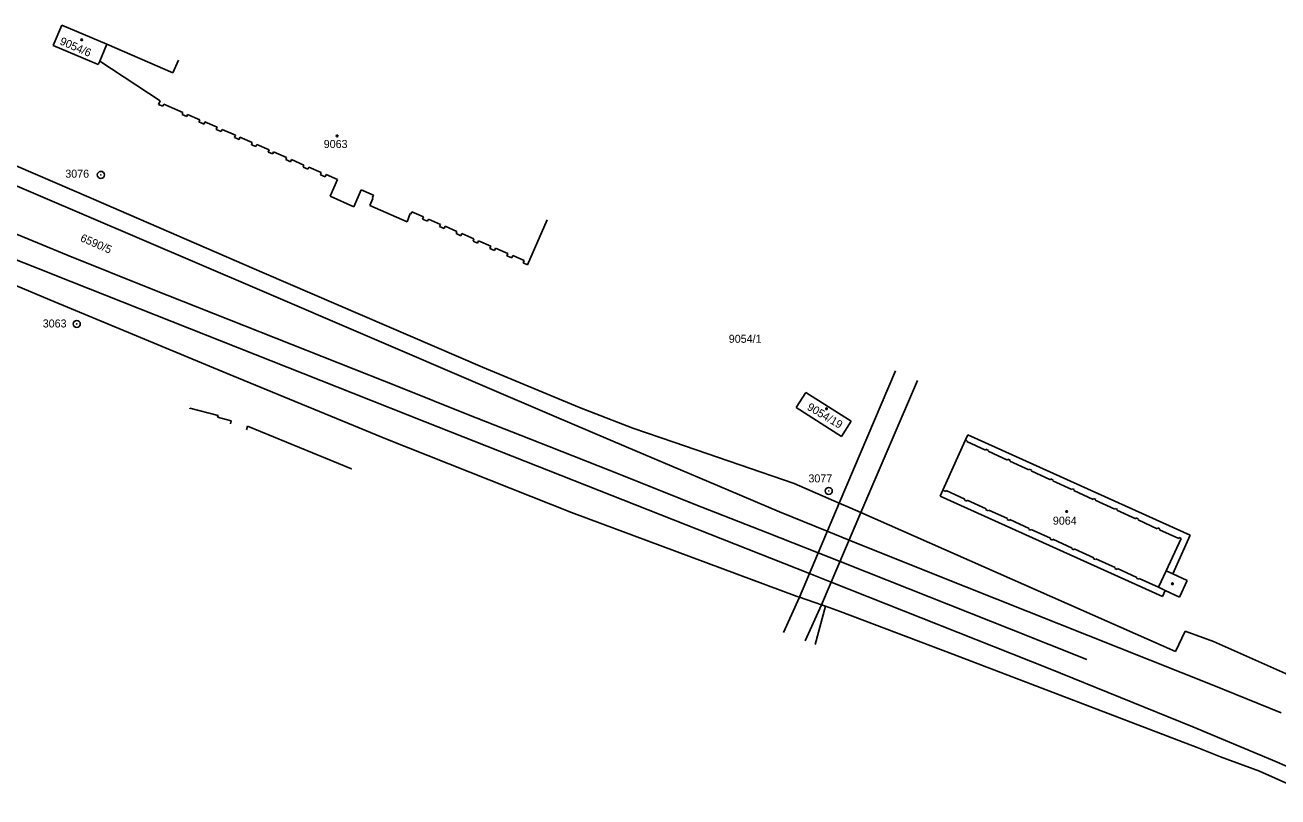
# Model space of a CAD drawing. Extents: x -825057 to -819383, y -1071633 to -1067888.
# Drawn here: x -823833 to -823566.9, y -1070247.2 to -1070083.4 of the extents above; entities that cross this region are included whole.
import ezdxf

# ---------------------------------------------------------------- set-up
doc = ezdxf.new("R2010")
doc.units = 0
for name, color, linetype in [('Vrstva 1', 7, 'Continuous'), ('Vrstva 10', 7, 'Continuous'), ('Vrstva 16', 7, 'Continuous'), ('Vrstva 17', 7, 'Continuous'), ('Vrstva 19', 7, 'Continuous'), ('Vrstva 24', 7, 'Continuous'), ('Vrstva 25', 7, 'Continuous'), ('Vrstva 4', 7, 'Continuous')]:
    doc.layers.add(name, color=color, linetype=linetype)

msp = doc.modelspace()

# ---------------------------------------------------------------- linework, layer by layer
at = {"layer": 'Vrstva 1'}
for p, q in [((-823825.21, -1070083.38), (-823827.05, -1070087.72)), ((-823815.62, -1070087.44), (-823825.21, -1070083.38)), ((-823817.15, -1070091.06), (-823815.62, -1070087.44)), ((-823815.62, -1070087.44), (-823801.63, -1070093.53)), ((-823827.05, -1070087.72), (-823817.46, -1070091.78)), ((-823817.46, -1070091.78), (-823817.15, -1070091.06)), ((-823804.33, -1070099.45), (-823817.15, -1070091.06)), ((-823801.63, -1070093.53), (-823800.4, -1070090.81)), ((-823804.67, -1070100.21), (-823804.33, -1070099.45)), ((-823803.77, -1070100.6), (-823804.67, -1070100.21)), ((-823803.57, -1070100.14), (-823803.77, -1070100.6)), ((-823799.47, -1070101.92), (-823803.57, -1070100.14)), ((-823799.66, -1070102.38), (-823799.47, -1070101.92)), ((-823798.69, -1070102.81), (-823799.66, -1070102.38)), ((-823798.49, -1070102.35), (-823798.69, -1070102.81)), ((-823795.91, -1070103.47), (-823798.49, -1070102.35)), ((-823796.11, -1070103.93), (-823795.91, -1070103.47)), ((-823795, -1070104.41), (-823796.11, -1070103.93)), ((-823794.8, -1070103.95), (-823795, -1070104.41)), ((-823792.22, -1070105.07), (-823794.8, -1070103.95)), ((-823792.42, -1070105.53), (-823792.22, -1070105.07)), ((-823791.34, -1070106), (-823792.42, -1070105.53)), ((-823791.14, -1070105.54), (-823791.34, -1070106)), ((-823788.34, -1070106.75), (-823791.14, -1070105.54)), ((-823818.96, -1070120.13), (-823850.43, -1070106.56)), ((-823788.54, -1070107.21), (-823788.34, -1070106.75)), ((-823787.57, -1070107.63), (-823788.54, -1070107.21)), ((-823787.37, -1070107.17), (-823787.57, -1070107.63)), ((-823784.74, -1070108.32), (-823787.37, -1070107.17)), ((-823784.94, -1070108.78), (-823784.74, -1070108.32)), ((-823784, -1070109.18), (-823784.94, -1070108.78)), ((-823783.8, -1070108.72), (-823784, -1070109.18)), ((-823781.17, -1070109.87), (-823783.8, -1070108.72)), ((-823781.37, -1070110.32), (-823781.17, -1070109.87)), ((-823780.41, -1070110.74), (-823781.37, -1070110.32)), ((-823780.21, -1070110.28), (-823780.41, -1070110.74)), ((-823777.45, -1070111.48), (-823780.21, -1070110.28)), ((-823777.65, -1070111.94), (-823777.45, -1070111.48)), ((-823776.62, -1070112.39), (-823777.65, -1070111.94)), ((-823776.42, -1070111.93), (-823776.62, -1070112.39)), ((-823773.77, -1070113.08), (-823776.42, -1070111.93)), ((-823773.97, -1070113.54), (-823773.77, -1070113.08)), ((-823772.94, -1070113.99), (-823773.97, -1070113.54)), ((-823772.74, -1070113.53), (-823772.94, -1070113.99)), ((-823770.09, -1070114.67), (-823772.74, -1070113.53)), ((-823770.29, -1070115.13), (-823770.09, -1070114.67)), ((-823769.28, -1070115.57), (-823770.29, -1070115.13)), ((-823769.08, -1070115.11), (-823769.28, -1070115.57)), ((-823766.66, -1070116.17), (-823769.08, -1070115.11)), ((-823768.19, -1070119.67), (-823766.66, -1070116.17)), ((-823761.61, -1070118.36), (-823763.18, -1070121.95)), ((-823758.99, -1070119.5), (-823761.61, -1070118.36)), ((-823782.23, -1070136), (-823818.96, -1070120.13)), ((-823763.18, -1070121.95), (-823768.19, -1070119.67)), ((-823759.76, -1070121.68), (-823759.11, -1070120.2)), ((-823751.87, -1070125.11), (-823759.76, -1070121.68)), ((-823759.18, -1070119.95), (-823758.99, -1070119.5)), ((-823759.11, -1070120.2), (-823759.18, -1070119.95)), ((-823751.24, -1070123.38), (-823751.87, -1070125.11)), ((-823751.05, -1070123.49), (-823751.24, -1070123.38)), ((-823750.85, -1070123.03), (-823751.05, -1070123.49)), ((-823748.36, -1070124.11), (-823750.85, -1070123.03)), ((-823748.56, -1070124.57), (-823748.36, -1070124.11)), ((-823747.54, -1070125.01), (-823748.56, -1070124.57)), ((-823747.34, -1070124.55), (-823747.54, -1070125.01)), ((-823744.75, -1070125.68), (-823747.34, -1070124.55)), ((-823722.11, -1070124.72), (-823726.26, -1070134.24)), ((-823744.95, -1070126.13), (-823744.75, -1070125.68)), ((-823744, -1070126.55), (-823744.95, -1070126.13)), ((-823743.8, -1070126.09), (-823744, -1070126.55)), ((-823741.27, -1070127.19), (-823743.8, -1070126.09)), ((-823741.47, -1070127.64), (-823741.27, -1070127.19)), ((-823827.74, -1070141.66), (-823859, -1070128.68)), ((-823740.45, -1070128.08), (-823741.47, -1070127.64)), ((-823740.26, -1070127.63), (-823740.45, -1070128.08)), ((-823737.65, -1070128.76), (-823740.26, -1070127.63)), ((-823737.85, -1070129.22), (-823737.65, -1070128.76)), ((-823736.87, -1070129.64), (-823737.85, -1070129.22)), ((-823736.67, -1070129.18), (-823736.87, -1070129.64)), ((-823734.05, -1070130.32), (-823736.67, -1070129.18)), ((-823734.25, -1070130.78), (-823734.05, -1070130.32)), ((-823733.27, -1070131.2), (-823734.25, -1070130.78)), ((-823733.07, -1070130.75), (-823733.27, -1070131.2)), ((-823730.47, -1070131.87), (-823733.07, -1070130.75)), ((-823730.67, -1070132.33), (-823730.47, -1070131.87)), ((-823729.63, -1070132.78), (-823730.67, -1070132.33)), ((-823729.43, -1070132.32), (-823729.63, -1070132.78)), ((-823726.99, -1070133.38), (-823729.43, -1070132.32)), ((-823727.19, -1070133.84), (-823726.99, -1070133.38)), ((-823726.26, -1070134.24), (-823727.19, -1070133.84)), ((-823735.81, -1070156.01), (-823782.23, -1070136)), ((-823790.07, -1070157.35), (-823827.74, -1070141.66)), ((-823715.25, -1070164.54), (-823735.81, -1070156.01)), ((-823756.05, -1070171.32), (-823790.07, -1070157.35)), ((-823669.2, -1070164.58), (-823667.12, -1070161.35)), ((-823667.12, -1070161.35), (-823657.54, -1070167.44)), ((-823798.01, -1070164.73), (-823798, -1070164.7)), ((-823798, -1070164.7), (-823792.02, -1070166.27)), ((-823703.89, -1070168.91), (-823715.25, -1070164.54)), ((-823659.56, -1070170.71), (-823669.2, -1070164.58)), ((-823792.02, -1070166.27), (-823792.12, -1070166.62)), ((-823792.12, -1070166.62), (-823789.21, -1070167.35)), ((-823789.21, -1070167.35), (-823789.37, -1070167.99)), ((-823785.98, -1070169.27), (-823785.79, -1070168.5)), ((-823785.79, -1070168.5), (-823763.69, -1070177.58)), ((-823695.2, -1070171.87), (-823703.89, -1070168.91)), ((-823657.54, -1070167.44), (-823659.56, -1070170.71)), ((-823716.94, -1070186.86), (-823756.05, -1070171.32)), ((-823669.62, -1070180.71), (-823695.2, -1070171.87)), ((-823638.04, -1070182.1), (-823633.29, -1070171.55)), ((-823633.29, -1070171.55), (-823633.23, -1070171.43)), ((-823633.23, -1070171.43), (-823632.76, -1070170.38)), ((-823632.76, -1070170.38), (-823585.51, -1070191.66)), ((-823763.72, -1070177.67), (-823763.69, -1070177.58)), ((-823660.1, -1070184.82), (-823669.62, -1070180.71)), ((-823638.61, -1070183.37), (-823638.04, -1070182.1)), ((-823657.7, -1070185.85), (-823660.1, -1070184.82)), ((-823655.46, -1070186.84), (-823657.7, -1070185.85)), ((-823591.36, -1070204.64), (-823638.61, -1070183.37)), ((-823669, -1070204.66), (-823716.94, -1070186.86)), ((-823588.59, -1070216.31), (-823655.46, -1070186.84)), ((-823585.51, -1070191.66), (-823589.21, -1070199.87)), ((-823589.21, -1070199.87), (-823586.15, -1070201.26)), ((-823586.15, -1070201.26), (-823587.74, -1070204.79)), ((-823590.79, -1070203.37), (-823591.36, -1070204.64)), ((-823587.74, -1070204.79), (-823590.79, -1070203.37)), ((-823668.52, -1070204.83), (-823669, -1070204.66)), ((-823663.8, -1070206.46), (-823668.52, -1070204.83)), ((-823665.14, -1070214.88), (-823662.99, -1070206.74)), ((-823662.99, -1070206.74), (-823663.8, -1070206.46)), ((-823659.82, -1070207.84), (-823662.99, -1070206.74)), ((-823635.91, -1070216.93), (-823659.82, -1070207.84)), ((-823586.59, -1070212.05), (-823588.59, -1070216.31)), ((-823580.56, -1070214.24), (-823586.59, -1070212.05)), ((-823547.49, -1070228.94), (-823580.56, -1070214.24)), ((-823584.03, -1070236.7), (-823635.91, -1070216.93)), ((-823579.03, -1070238.68), (-823584.03, -1070236.7)), ((-823570.77, -1070241.76), (-823579.03, -1070238.68)), ((-823567.45, -1070243.25), (-823570.77, -1070241.76)), ((-823558.51, -1070247.2), (-823567.45, -1070243.25))]:
    msp.add_line(p, q, dxfattribs=at)
at = {"layer": 'Vrstva 10'}
for p, q in [((-823820.48, -1070123.67), (-823852.48, -1070110)), ((-823783.73, -1070139.36), (-823820.48, -1070123.67)), ((-823823.85, -1070132.28), (-823836.87, -1070126.94)), ((-823827.54, -1070136.13), (-823842.18, -1070130.3)), ((-823806.26, -1070139.38), (-823823.85, -1070132.28)), ((-823827.03, -1070136.31), (-823827.54, -1070136.13)), ((-823808.63, -1070143.6), (-823827.03, -1070136.31)), ((-823753.25, -1070160.33), (-823806.26, -1070139.38)), ((-823735.84, -1070159.86), (-823783.73, -1070139.36)), ((-823763.38, -1070161.51), (-823808.63, -1070143.6)), ((-823747.99, -1070167.59), (-823763.38, -1070161.51)), ((-823739.17, -1070165.99), (-823753.25, -1070160.33)), ((-823720.59, -1070166.37), (-823735.84, -1070159.86)), ((-823721.67, -1070172.83), (-823739.17, -1070165.99)), ((-823705.3, -1070172.89), (-823720.59, -1070166.37)), ((-823666.39, -1070199.77), (-823747.99, -1070167.59)), ((-823706.21, -1070178.94), (-823721.67, -1070172.83)), ((-823685.94, -1070181.1), (-823705.3, -1070172.89)), ((-823690.84, -1070185.04), (-823706.21, -1070178.94)), ((-823672.75, -1070186.66), (-823685.94, -1070181.1)), ((-823675.26, -1070191.16), (-823690.84, -1070185.04)), ((-823662.6, -1070190.76), (-823672.75, -1070186.66)), ((-823675.26, -1070191.16), (-823664.55, -1070195.39)), ((-823657.97, -1070192.73), (-823662.6, -1070190.76)), ((-823639.76, -1070200), (-823657.97, -1070192.73)), ((-823664.55, -1070195.39), (-823659.88, -1070197.23)), ((-823659.88, -1070197.23), (-823654.34, -1070199.42)), ((-823661.74, -1070201.61), (-823666.39, -1070199.77)), ((-823615.68, -1070219.86), (-823661.74, -1070201.61)), ((-823654.34, -1070199.42), (-823623.42, -1070211.64)), ((-823580.83, -1070223.42), (-823639.76, -1070200)), ((-823623.42, -1070211.64), (-823607.42, -1070218.06)), ((-823584.9, -1070232.36), (-823615.68, -1070219.86)), ((-823566.15, -1070229.34), (-823580.83, -1070223.42)), ((-823568.02, -1070239.41), (-823584.9, -1070232.36)), ((-823556.91, -1070244.25), (-823568.02, -1070239.41))]:
    msp.add_line(p, q, dxfattribs=at)
at = {"layer": 'Vrstva 24'}
for centre, radius in [((-823816.92, -1070115.18), 0.75), ((-823816.92, -1070115.18), 0.0327), ((-823822.04, -1070146.81), 0.75), ((-823822.04, -1070146.81), 0.0327), ((-823662.27, -1070182.26), 0.75), ((-823662.27, -1070182.26), 0.0327)]:
    msp.add_circle(centre, radius, dxfattribs=at)
at = {"layer": 'Vrstva 25'}
for centre in [(-823821.01, -1070086.5), (-823766.73, -1070106.9), (-823662.76, -1070164.82), (-823611.74, -1070186.62), (-823589.26, -1070201.96)]:
    msp.add_circle(centre, 0.175, dxfattribs=at)
at = {"layer": 'Vrstva 4'}
for p, q in [((-823648.08, -1070156.79), (-823660.1, -1070184.82)), ((-823643.45, -1070158.79), (-823655.46, -1070186.84)), ((-823633.23, -1070171.43), (-823632.85, -1070171.6)), ((-823632.85, -1070171.6), (-823632.93, -1070171.78)), ((-823632.93, -1070171.78), (-823628.96, -1070173.6)), ((-823628.96, -1070173.6), (-823628.88, -1070173.41)), ((-823628.88, -1070173.41), (-823628.34, -1070173.66)), ((-823628.34, -1070173.66), (-823628.42, -1070173.84)), ((-823628.42, -1070173.84), (-823624.33, -1070175.71)), ((-823624.33, -1070175.71), (-823624.25, -1070175.53)), ((-823624.25, -1070175.53), (-823623.76, -1070175.75)), ((-823623.76, -1070175.75), (-823623.84, -1070175.94)), ((-823623.84, -1070175.94), (-823619.79, -1070177.79)), ((-823619.79, -1070177.79), (-823619.71, -1070177.61)), ((-823619.71, -1070177.61), (-823619.19, -1070177.84)), ((-823619.19, -1070177.84), (-823619.28, -1070178.02)), ((-823619.28, -1070178.02), (-823615.17, -1070179.9)), ((-823615.17, -1070179.9), (-823615.09, -1070179.72)), ((-823615.09, -1070179.72), (-823614.59, -1070179.95)), ((-823614.59, -1070179.95), (-823614.67, -1070180.13)), ((-823614.67, -1070180.13), (-823610.62, -1070181.98)), ((-823637.43, -1070182.37), (-823638.04, -1070182.1)), ((-823637.35, -1070182.19), (-823637.43, -1070182.37)), ((-823633.34, -1070184.01), (-823637.35, -1070182.19)), ((-823610.62, -1070181.98), (-823610.53, -1070181.8)), ((-823610.53, -1070181.8), (-823610.14, -1070181.98)), ((-823610.14, -1070181.98), (-823610.22, -1070182.16)), ((-823610.22, -1070182.16), (-823606.1, -1070184.04)), ((-823660.1, -1070184.82), (-823668.52, -1070204.83)), ((-823633.43, -1070184.2), (-823633.34, -1070184.01)), ((-823632.93, -1070184.42), (-823633.43, -1070184.2)), ((-823632.85, -1070184.24), (-823632.93, -1070184.42)), ((-823628.82, -1070186.07), (-823632.85, -1070184.24)), ((-823606.1, -1070184.04), (-823606.02, -1070183.86)), ((-823606.02, -1070183.86), (-823605.57, -1070184.07)), ((-823605.57, -1070184.07), (-823605.65, -1070184.25)), ((-823605.65, -1070184.25), (-823601.51, -1070186.14)), ((-823601.51, -1070186.14), (-823601.43, -1070185.96)), ((-823601.43, -1070185.96), (-823600.97, -1070186.17)), ((-823655.46, -1070186.84), (-823663.8, -1070206.46)), ((-823628.9, -1070186.25), (-823628.82, -1070186.07)), ((-823628.35, -1070186.5), (-823628.9, -1070186.25)), ((-823628.27, -1070186.32), (-823628.35, -1070186.5)), ((-823624.3, -1070188.12), (-823628.27, -1070186.32)), ((-823624.39, -1070188.3), (-823624.3, -1070188.12)), ((-823623.91, -1070188.52), (-823624.39, -1070188.3)), ((-823623.83, -1070188.34), (-823623.91, -1070188.52)), ((-823619.68, -1070190.23), (-823623.83, -1070188.34)), ((-823600.97, -1070186.17), (-823601.06, -1070186.35)), ((-823601.06, -1070186.35), (-823597.05, -1070188.18)), ((-823597.05, -1070188.18), (-823596.97, -1070188)), ((-823596.97, -1070188), (-823596.48, -1070188.22)), ((-823596.48, -1070188.22), (-823596.56, -1070188.4)), ((-823596.56, -1070188.4), (-823592.48, -1070190.27)), ((-823619.76, -1070190.41), (-823619.68, -1070190.23)), ((-823619.35, -1070190.6), (-823619.76, -1070190.41)), ((-823619.26, -1070190.41), (-823619.35, -1070190.6)), ((-823615.16, -1070192.28), (-823619.26, -1070190.41)), ((-823592.48, -1070190.27), (-823592.4, -1070190.09)), ((-823592.4, -1070190.09), (-823591.93, -1070190.3)), ((-823591.93, -1070190.3), (-823592.01, -1070190.48)), ((-823592.01, -1070190.48), (-823587.94, -1070192.34)), ((-823615.24, -1070192.46), (-823615.16, -1070192.28)), ((-823614.78, -1070192.67), (-823615.24, -1070192.46)), ((-823614.7, -1070192.49), (-823614.78, -1070192.67)), ((-823610.54, -1070194.38), (-823614.7, -1070192.49)), ((-823587.41, -1070192.37), (-823590.61, -1070199.23)), ((-823587.94, -1070192.34), (-823587.86, -1070192.16)), ((-823587.86, -1070192.16), (-823587.41, -1070192.37)), ((-823610.62, -1070194.56), (-823610.54, -1070194.38)), ((-823610.22, -1070194.74), (-823610.62, -1070194.56)), ((-823610.14, -1070194.56), (-823610.22, -1070194.74)), ((-823605.94, -1070196.47), (-823610.14, -1070194.56)), ((-823606.02, -1070196.65), (-823605.94, -1070196.47)), ((-823605.61, -1070196.84), (-823606.02, -1070196.65)), ((-823605.53, -1070196.65), (-823605.61, -1070196.84)), ((-823601.42, -1070198.52), (-823605.53, -1070196.65)), ((-823601.51, -1070198.7), (-823601.42, -1070198.52)), ((-823601.04, -1070198.92), (-823601.51, -1070198.7)), ((-823600.95, -1070198.74), (-823601.04, -1070198.92)), ((-823596.85, -1070200.6), (-823600.95, -1070198.74)), ((-823590.61, -1070199.23), (-823592.23, -1070202.7)), ((-823589.21, -1070199.87), (-823590.61, -1070199.23)), ((-823596.93, -1070200.78), (-823596.85, -1070200.6)), ((-823596.43, -1070201.01), (-823596.93, -1070200.78)), ((-823596.35, -1070200.83), (-823596.43, -1070201.01)), ((-823592.23, -1070202.7), (-823596.35, -1070200.83)), ((-823592.23, -1070202.7), (-823590.79, -1070203.37)), ((-823668.52, -1070204.83), (-823671.91, -1070212.33)), ((-823663.8, -1070206.46), (-823667.28, -1070214.07))]:
    msp.add_line(p, q, dxfattribs=at)

# ---------------------------------------------------------------- texts
at = {"layer": 'Vrstva 16'}
msp.add_text('6590/5', height=1.7, rotation=336.6, dxfattribs=at).set_placement((-823821.436, -1070129.173))
msp.add_text('9054/1', height=1.7, dxfattribs=at).set_placement((-823683.515, -1070150.81))
at = {"layer": 'Vrstva 17'}
for s, p in [('3076', (-823824.474, -1070115.77)), ('3063', (-823829.264, -1070147.56)), ('3077', (-823666.6, -1070180.44))]:
    msp.add_text(s, height=1.7, dxfattribs=at).set_placement(p)
at = {"layer": 'Vrstva 19'}
for s, rotation, p in [('9054/6', 336.6, (-823825.798, -1070087.41)), ('9054/19', 329.2182, (-823667.05, -1070164.901))]:
    msp.add_text(s, height=1.7, rotation=rotation, dxfattribs=at).set_placement(p)
for s, p in [('9063', (-823769.572, -1070109.47)), ('9064', (-823614.666, -1070189.41))]:
    msp.add_text(s, height=1.7, dxfattribs=at).set_placement(p)

doc.saveas('drawing.dxf')
